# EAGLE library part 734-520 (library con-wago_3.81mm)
Serie 734, Federleiste mit geraden Einlötstiften / Series 734, Female connector with straight solder pins Polzahl / Pole No.: 20 Bemessungsspannung / Rated Voltage: 160 V Nennstrom / Nominal Current: 10 A Lötstiftlänge: / Solder Pin Length: 3.8 mm Farbe / Color: orange / orange Stand: 01.01.2012. Die jeweils aktuellen Daten zu diesem Artikel finden Sie in unserem Produktkatalog, den Sie unter www.wago.com einsehen können. As of: 01/01/2012. Please find the newest data for this article in our product catalogue, which can be viewed under www.wago.com.
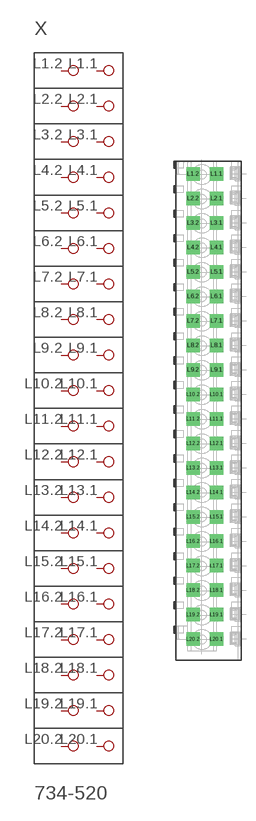
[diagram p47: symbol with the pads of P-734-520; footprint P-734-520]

Designator prefix X

## 734-520  [P-734-520]
L1.1  P1.1
L1.2  P1.2
L2.1  P2.1
L2.2  P2.2
L3.1  P3.1
L3.2  P3.2
L4.1  P4.1
L4.2  P4.2
L5.1  P5.1
L5.2  P5.2
L6.1  P6.1
L6.2  P6.2
L7.1  P7.1
L7.2  P7.2
L8.1  P8.1
L8.2  P8.2
L9.1  P9.1
L9.2  P9.2
L10.1  P10.1
L10.2  P10.2
L11.1  P11.1
L11.2  P11.2
L12.1  P12.1
L12.2  P12.2
L13.1  P13.1
L13.2  P13.2
L14.1  P14.1
L14.2  P14.2
L15.1  P15.1
L15.2  P15.2
L16.1  P16.1
L16.2  P16.2
L17.1  P17.1
L17.2  P17.2
L18.1  P18.1
L18.2  P18.2
L19.1  P19.1
L19.2  P19.2
L20.1  P20.1
L20.2  P20.2

## Footprint P-734-520 (pad centres in mm)
drill 1.4 square: L1.1 1.002,36.722; L1.2 -2.648,36.722; L2.1 1.002,32.912; L2.2 -2.648,32.912; L3.1 1.002,29.102; L3.2 -2.648,29.102; L4.1 1.002,25.292; L4.2 -2.648,25.292; L5.1 1.002,21.482; L5.2 -2.648,21.482; L6.1 1.002,17.672; L6.2 -2.648,17.672; L7.1 1.002,13.862; L7.2 -2.648,13.862; L8.1 1.002,10.052; L8.2 -2.648,10.052; L9.1 1.002,6.242; L9.2 -2.648,6.242; L10.1 1.002,2.432; L10.2 -2.648,2.432; L11.1 1.002,-1.378; L11.2 -2.648,-1.378; L12.1 1.002,-5.188; L12.2 -2.648,-5.188; L13.1 1.002,-8.998; L13.2 -2.648,-8.998; L14.1 1.002,-12.808; L14.2 -2.648,-12.808; L15.1 1.002,-16.618; L15.2 -2.648,-16.618; L16.1 1.002,-20.428; L16.2 -2.648,-20.428; L17.1 0.992,-24.238; L17.2 -2.658,-24.238; L18.1 0.992,-28.048; L18.2 -2.658,-28.048; L19.1 0.992,-31.858; L19.2 -2.658,-31.858; L20.1 0.992,-35.668; L20.2 -2.658,-35.668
